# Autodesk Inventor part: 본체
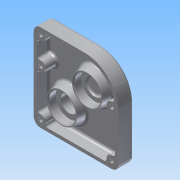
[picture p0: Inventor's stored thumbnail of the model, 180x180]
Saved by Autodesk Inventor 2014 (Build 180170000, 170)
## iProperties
Created: 2015-11
Part Number: 본체
Material: 알루미늄 6061
Document SubType Name: Modeling
Designer: net
Density: 2.71 g/cm^3
Appearance: 알루미늄 - 평지
Mass: 247.553 g
Surface Area: 389.424 cm^2
Volume: 91.3479 cm^3
Author: net
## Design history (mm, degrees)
sketch "스케치1"
  geometry: L1 (-50, 51.5)-(-50, -51.5); L2 (-50, -51.5)-(50, -51.5); L3 (50, -51.5)-(50, 11.5); L4 (-50, 51.5)-(10, 51.5); A1 r 40 centre (10, 11.5) between (50, 11.5) and (10, 51.5); 3 further points
  constraints: 8 end point, 2 midpoint, 2 perpendicular, 2 point on circle, 1 centre point, 1 horizontal alignment, 1 parallel, 1 tangent, 1 vertical, 1 vertical alignment
  dimensions: "d0" = 103 distance between parallel lines of L2 L4; "d1" = 100 distance of L1.end L2.end; "d2" = 40 radius of A1; "d3" = 63.00001 distance from line of L2 A1.centre
extrude "돌출1" new body sketch "스케치1" stored distance "d4" = 18; taper "d5" = 0 deg
fillet "모깎기1" dims "d6" = 8
sketch "스케치2"
  geometry: L1 (50, -43.5)-(50, 11.5) reference; L2 (10, 51.5)-(-42, 51.5) reference; L3 (-50, 43.5)-(-50, -43.5) reference; L4 (-42, -51.5)-(42, -51.5) reference; L5 (46, 7.028)-(46, -39.028); L6 (37.528, -47.5)-(-37.528, -47.5); L7 (-46, -39.028)-(-46, 7.028); L8 (-46, 15.972)-(-46, 39.028); L9 (10, 47.5)-(-37.528, 47.5); A1 r 8 centre (42, -43.5) between (42, -51.5) and (50, -43.5) reference; A2 r 40 centre (10, 11.5) between (50, 11.5) and (10, 51.5) reference; A3 r 8 centre (-42, 43.5) between (-42, 51.5) and (-50, 43.5) reference; A4 r 8 centre (-42, -43.5) between (-50, -43.5) and (-42, -51.5) reference; A5 r 6 centre (-42, 43.5) between (-46, 39.028) and (-37.528, 47.5); A6 r 6 centre (-42, -43.5) between (-37.528, -47.5) and (-46, -39.028); A7 r 6 centre (42, -43.5) between (46, -39.028) and (37.528, -47.5); A8 r 6 centre (42, 11.5) between (45.688, 16.233) and (46, 7.028); A9 r 6 centre (-42, 11.5) between (-46, 7.028) and (-46, 15.972); A10 r 36 centre (10, 11.5) between (45.688, 16.233) and (10, 47.5); 1 further point
  constraints: 12 point on circle, 10 end point, 6 centre point, 4 equal radius, 3 coincident, 2 vertical alignment, 1 perpendicular
  dimensions: "d8" = 6 radius of A5; "d9" = 32 vertical distance of A8.centre A3.centre; "d10" = 63 distance from line of L4 A9.centre; "d12" = 36 radius of A10; "d13" = 4 distance between parallel lines of L2 L9; "d14" = 4 distance between parallel lines of L8 L3; "d15" = 4 distance between parallel lines of L7 L3; "d16" = 4 distance between parallel lines of L4 L6; "d17" = 4 distance between parallel lines of L5 L1
extrude "돌출2" cut sketch "스케치2" distance "d18" = 14; taper "d19" = 0 deg
sketch "스케치4"
  geometry: C1 r 20 at (10, 11.5); A1 r 36 centre (10, 11.5) between (45.688, 16.233) and (10, 47.5) reference; 1 further point
  constraints: 1 centre point, 1 coincident
  dimensions: "d23" = 40 diameter of C1
extrude "돌출3" join sketch "스케치4" distance "d24" = 11; taper "d25" = -10 deg
sketch "스케치5"
  geometry: C1 r 18.06 at (0, 0) reference; C2 r 16 at (0, 0); C3 r 11 at (0, 0); 1 further point
  constraints: 2 centre point, 2 coincident
  dimensions: "d27" = 32 diameter of C2; "d28" = 22 diameter of C3
extrude "돌출4" cut sketch "스케치5" distance "d29" = 9; taper "d30" = 0 deg
extrude "돌출5" cut sketch "스케치5" distance "d31" = 11; taper "d32" = 0 deg
sketch "스케치6"
  geometry: L1 (-50, 43.5)-(-50, -43.5) reference; L2 (-42, -51.5)-(42, -51.5) reference; C1 r 20 at (-20, -21.5); 1 further point
  constraints: 1 centre point
  dimensions: "d33" = 30 distance from line of L1 C1.centre; "d34" = 30 distance from line of L2 C1.centre; "d35" = 40 diameter of C1
extrude "돌출6" join sketch "스케치6" distance "d36" = 11; taper "d37" = -10 deg
sketch "스케치7"
  geometry: C1 r 18.06 at (0, 0) reference; C2 r 16 at (0, 0); 1 further point
  constraints: 1 centre point, 1 coincident
  dimensions: "d38" = 32 diameter of C2
extrude "돌출7" cut sketch "스케치7" distance "d39" = 9; taper "d40" = 0 deg
sketch "스케치8"
  geometry: C1 r 20 at (20, -21.5) reference; C2 r 25 at (20, -21.5); 1 further point
  constraints: 1 centre point, 1 coincident
  dimensions: "d41" = 50 diameter of C2
extrude "돌출8" join sketch "스케치8" distance "d42" = 15; taper "d43" = -10 deg
sketch "스케치9"
  geometry: C1 r 22.355 at (0, 0) reference; C2 r 14 at (0, 0); C3 r 12 at (0, 0); C4 r 12 at (0, 0); C5 r 10 at (0, 0); 1 further point
  constraints: 4 centre point, 4 coincident, 1 concentric
  dimensions: "d44" = 28 diameter of C2; "d45" = 24 diameter of C3; "d46" = 20 diameter of C5
extrude "돌출9" cut sketch "스케치9" distance "d47" = 11; taper "d48" = 0 deg
extrude "돌출10" cut sketch "스케치9" distance "d49" = 13; taper "d50" = 0 deg
extrude "돌출11" cut sketch "스케치9" stored distance "d51" = 13; taper "d52" = 0 deg
sketch "스케치10" dims "d53" = 36
  geometry: L1 (0, 0)-(0, 18); C1 r 22.355 at (0, 0) reference; 2 further points
  constraints: 2 coincident, 2 end point, 1 vertical, 1 vertical alignment, 2 other
hole "구멍1" sketch "스케치10" at (0, 18) diameter "d54" = 2.459; stored, may be unused: countersink angle "d58" = 90 deg, drill point angle "d60" = 118 deg; dims "d55" = 8, "d56" = 4, "d57" = 2, "d59" = 10
sketch "스케치13"
  geometry: L1 (37.528, 47.5)-(-10, 47.5) reference; L2 (-46, 7.028)-(-46, -39.028) reference; L3 (-37.528, -47.5)-(37.528, -47.5) reference; L4 (46, -39.028)-(46, 7.028) reference; L5 (46, 15.972)-(46, 39.028) reference; L6 (-50, -43.5)-(-50, 11.5) reference; L7 (-10, 51.5)-(42, 51.5) reference; L8 (50, 43.5)-(50, -43.5) reference; L9 (42, -51.5)-(-42, -51.5) reference; A1 r 36 centre (-10, 11.5) between (-10, 47.5) and (-45.688, 16.233) reference; A2 r 6 centre (-42, 11.5) between (-46, 7.028) and (-45.688, 16.233) reference; A3 r 6 centre (-42, -43.5) between (-37.528, -47.5) and (-46, -39.028) reference; A4 r 6 centre (42, -43.5) between (46, -39.028) and (37.528, -47.5) reference; A5 r 6 centre (42, 11.5) between (46, 15.972) and (46, 7.028) reference; A6 r 6 centre (42, 43.5) between (37.528, 47.5) and (46, 39.028) reference; A7 r 8 centre (-42, -43.5) between (-50, -43.5) and (-42, -51.5) reference; A8 r 40 centre (-10, 11.5) between (-10, 51.5) and (-50, 11.5) reference; A9 r 8 centre (42, 43.5) between (50, 43.5) and (42, 51.5) reference; A10 r 8 centre (42, -43.5) between (42, -51.5) and (50, -43.5) reference; 6 further points
  constraints: 5 coincident
hole "구멍3" sketch "스케치13" at (-42, 11.5), (-42, -43.5), (42, -43.5), (42, 11.5), (42, 43.5) diameter "d86" = 4.5; stored, may be unused: countersink angle "d90" = 90 deg, drill point angle "d92" = 118 deg; dims "d87" = 6, "d88" = 8, "d89" = 4.4, "d91" = 8
sketch "스케치12"
  geometry: L1 (50, -43.5)-(50, 43.5) reference; L2 (42, 51.5)-(-10, 51.5) reference; 2 further points
  constraints: 1 other
  dimensions: "d71" = 40 distance from line of L1 point (10, 31.5); "d72" = 20 distance from line of L2 point (10, 31.5)
feature "엠보싱1" sketch "스케치12" dims "d0" = 103, "d1" = 100, "d2" = 40, "d3" = 63.00001, "d73" = 0.5, "d74" = 0
fillet "모깎기2" dims "d75" = 3
fillet "모깎기3" dims "d76" = 3
fillet "모깎기4" dims "d77" = 0.3
fillet "모깎기5" dims "d78" = 0.3
fillet "모깎기6" dims "d79" = 3
chamfer "모따기1" distance "d80" = 1; stored, may be unused: second distance "d81" = 2, angle "d82" = 45 deg
fillet "모깎기7" dims "d83" = 3
fillet "모깎기8" dims "d84" = 3
fillet "모깎기9" dims "d85" = 3
node "솔리드1"
pattern_circular "원형 패턴1" dims angle "d62" = 360 deg
node "투영된 루프1"
